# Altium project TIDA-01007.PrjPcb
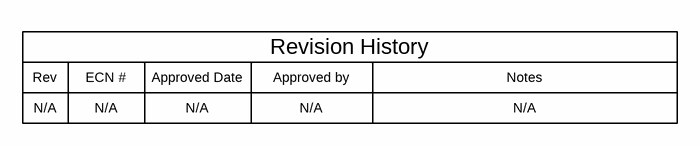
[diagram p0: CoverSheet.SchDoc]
CopyrightYear: 2015; EVM_Orderable: N/A; PCB_Layout: Summer Su; PCB_Rev: E1; PRJ_Customer: Public Release; PRJ_Engineer: Summer Su; PRJ_Number: TIDA-01007; PRJ_Title: Automotive EMC Compatible Rear Light with Sequential and Turn Function; SCH_Rev: E1; TechSupport: http://www.ti.com/support; TID: TIDA-01007
3 sheets, 83 parts. Net scope: global (net labels, ports and power ports of the same name join across sheets).
Board file: TIDA-01007.PcbDoc
Sheets:
  CoverSheet.SchDoc
  TIDA-01007_CoverSheet.SchDoc
  TID_Hardware.SchDoc

## Sheet CoverSheet.SchDoc
size 431 x 279 mm; Date: Not shown in title block; ApprovedBy: Not shown in title block; CheckedBy: Not shown in title block; Author: Not shown in title block; CompanyName: Not shown in title block; Engineer: Not shown in title block; Organization: Not shown in title block; Address1: Not shown in title block; Address2: Not shown in title block; Address3: Not shown in title block; Address4: Not shown in title block; DocumentNumber: 1; Revision: Use project parameter SCH_Rev; SheetNumber: 1; SheetTotal: 3; PageSetup: Record=PageOptions¦CenterHorizontal=True¦CenterVertical=True¦PrintScale=1.00¦XCorrection=1.00¦YCorrection=1.00¦PrintKind=0¦BorderSize=5000000¦LeftOffset=0¦BottomOffset=0¦Orientation=2¦PaperLength=1000¦PaperWidth=1000¦Scale=100¦PaperSource=15¦PrintQuality=600¦MediaType=1¦DitherType=10¦PaperKind=Letter¦PrintScaleMode=1

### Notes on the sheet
- Rev
- N/A
- ECN #
- Approved Date
- Approved by
- Revision History
- Notes

## Sheet TIDA-01007_CoverSheet.SchDoc
size 431 x 279 mm; Date: Not shown in title block; ApprovedBy: Not shown in title block; CheckedBy: Not shown in title block; Author: Not shown in title block; CompanyName: Not shown in title block; Engineer: Summer Su; Organization: Not shown in title block; Address1: Not shown in title block; Address2: Not shown in title block; Address3: Not shown in title block; Address4: Not shown in title block; DocumentNumber: 1; Revision: Use project parameter SCH_Rev; SheetNumber: 2; SheetTotal: 3; PageSetup: Record=PageOptions¦CenterHorizontal=True¦CenterVertical=True¦PrintScale=0.64¦XCorrection=1.00¦YCorrection=1.00¦PrintKind=0¦BorderSize=5000000¦LeftOffset=0¦BottomOffset=0¦Orientation=2¦PaperLength=1000¦PaperWidth=1000¦Scale=100¦PaperSource=15¦PrintQuality=600¦MediaType=1¦DitherType=10¦PrintScaleMode=1¦PaperKind=Letter
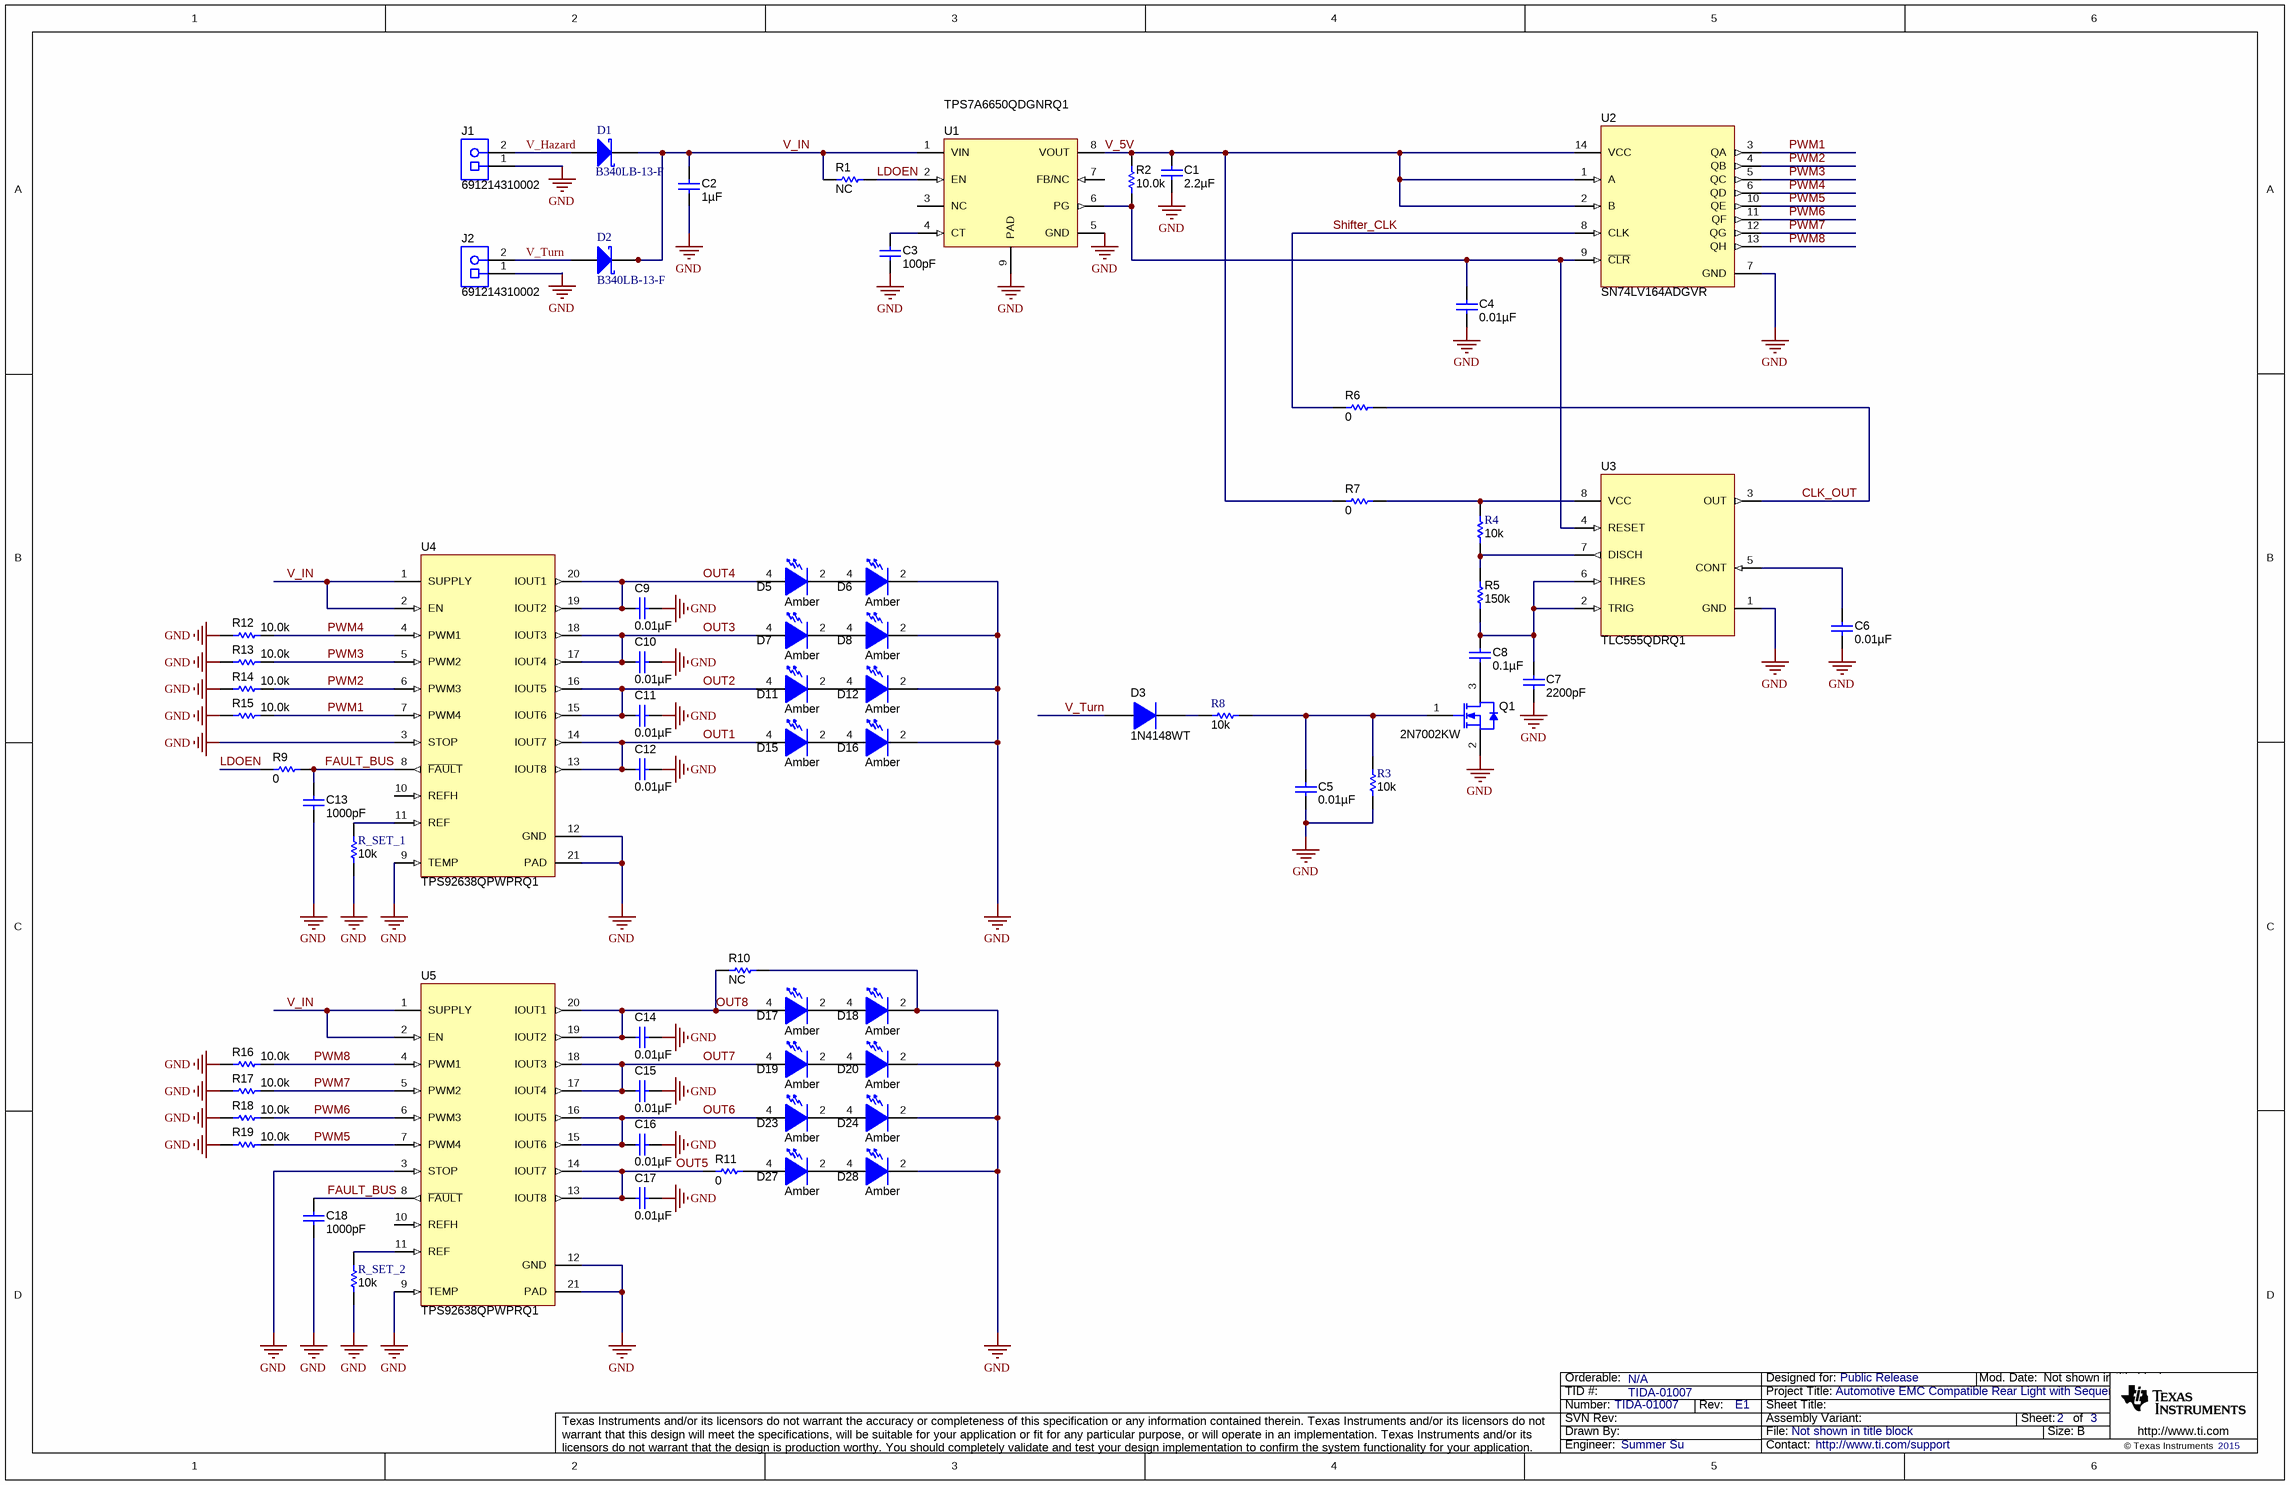
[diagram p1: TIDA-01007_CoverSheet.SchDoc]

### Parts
C1  ValueDisplayed: 2.2µF  [0805_HV]  (hidden comment: 0805YD225KAT2A)
C2  ValueDisplayed: 1µF  [0805_HV]  (hidden comment: 08055C105KAT2A)
C3  ValueDisplayed: 100pF  [0603]  (hidden comment: 06033C101KAT2A)
C4  ValueDisplayed: 0.01µF  [0603]  (hidden comment: CL10B103KB8NCNC)
C5  ValueDisplayed: 0.01µF  [0603]  (hidden comment: CL10B103KB8NCNC)
C6  ValueDisplayed: 0.01µF  [0603]  (hidden comment: CL10B103KB8NCNC)
C7  ValueDisplayed: 2200pF  [0603]  (hidden comment: C0603C222K5RAC)
C8  ValueDisplayed: 0.1µF  [0603]  (hidden comment: 0603YC104JAT2A)
C9  ValueDisplayed: 0.01µF  [0603]  (hidden comment: C0603C103K5RACTU)
C10  ValueDisplayed: 0.01µF  [0603]  (hidden comment: C0603C103K5RACTU)
C11  ValueDisplayed: 0.01µF  [0603]  (hidden comment: C0603C103K5RACTU)
C12  ValueDisplayed: 0.01µF  [0603]  (hidden comment: C0603C103K5RACTU)
C13  ValueDisplayed: 1000pF  [0603]  (hidden comment: C0603X102K5RACTU)
C14  ValueDisplayed: 0.01µF  [0603]  (hidden comment: C0603C103K5RACTU)
C15  ValueDisplayed: 0.01µF  [0603]  (hidden comment: C0603C103K5RACTU)
C16  ValueDisplayed: 0.01µF  [0603]  (hidden comment: C0603C103K5RACTU)
C17  ValueDisplayed: 0.01µF  [0603]  (hidden comment: C0603C103K5RACTU)
C18  ValueDisplayed: 1000pF  [0603]  (hidden comment: C0603X102K5RACTU)
D1  B340LB-13-F  [SMB]
D2  B340LB-13-F  [SMB]
D3  1N4148WT  [Fairchild_SOD-523F]
D5  value Amber  [LED_PowerTOPLED_GF_lens]  (hidden comment: LA E63F-EBGA-24-1-Z)
D6  value Amber  [LED_PowerTOPLED_GF_lens]  (hidden comment: LA E63F-EBGA-24-1-Z)
D7  value Amber  [LED_PowerTOPLED_GF_lens]  (hidden comment: LA E63F-EBGA-24-1-Z)
D8  value Amber  [LED_PowerTOPLED_GF_lens]  (hidden comment: LA E63F-EBGA-24-1-Z)
D11  value Amber  [LED_PowerTOPLED_GF_lens]  (hidden comment: LA E63F-EBGA-24-1-Z)
D12  value Amber  [LED_PowerTOPLED_GF_lens]  (hidden comment: LA E63F-EBGA-24-1-Z)
D15  value Amber  [LED_PowerTOPLED_GF_lens]  (hidden comment: LA E63F-EBGA-24-1-Z)
D16  value Amber  [LED_PowerTOPLED_GF_lens]  (hidden comment: LA E63F-EBGA-24-1-Z)
D17  value Amber  [LED_PowerTOPLED_GF_lens]  (hidden comment: LA E63F-EBGA-24-1-Z)
D18  value Amber  [LED_PowerTOPLED_GF_lens]  (hidden comment: LA E63F-EBGA-24-1-Z)
D19  value Amber  [LED_PowerTOPLED_GF_lens]  (hidden comment: LA E63F-EBGA-24-1-Z)
D20  value Amber  [LED_PowerTOPLED_GF_lens]  (hidden comment: LA E63F-EBGA-24-1-Z)
D23  value Amber  [LED_PowerTOPLED_GF_lens]  (hidden comment: LA E63F-EBGA-24-1-Z)
D24  value Amber  [LED_PowerTOPLED_GF_lens]  (hidden comment: LA E63F-EBGA-24-1-Z)
D27  value Amber  [LED_PowerTOPLED_GF_lens]  (hidden comment: LA E63F-EBGA-24-1-Z)
D28  value Amber  [LED_PowerTOPLED_GF_lens]  (hidden comment: LA E63F-EBGA-24-1-Z)
J1  691214310002  [Wurth_691214310002]
J2  691214310002  [Wurth_691214310002]
Q1  2N7002KW  [SOT-323]
R1  ValueDisplayed: NC  [0603]  (hidden comment: RG1608P-103-B-T5)
R2  ValueDisplayed: 10.0k  [0603]  (hidden comment: RG1608P-103-B-T5)
R3  value 10k  [0603]  (hidden comment: CRCW060310K0FKEA)
R4  value 10k  [0603]  (hidden comment: CRCW060310K0FKEA)
R5  ValueDisplayed: 150k  [0603]  (hidden comment: CRCW0603150KFKEA)
R6  ValueDisplayed: 0  [0603]  (hidden comment: CRCW06030000Z0EA)
R7  ValueDisplayed: 0  [0603]  (hidden comment: CRCW06030000Z0EA)
R8  value 10k  [0603]  (hidden comment: CRCW060310K0FKEA)
R9  ValueDisplayed: 0  [0603]  (hidden comment: CRCW06030000Z0EA)
R10  ValueDisplayed: NC  [0805_HV]  (hidden comment: CRCW08050000Z0EA)
R11  ValueDisplayed: 0  [0805_HV]  (hidden comment: CRCW08050000Z0EA)
R12  ValueDisplayed: 10.0k  [0603]  (hidden comment: RG1608P-103-B-T5)
R13  ValueDisplayed: 10.0k  [0603]  (hidden comment: RG1608P-103-B-T5)
R14  ValueDisplayed: 10.0k  [0603]  (hidden comment: RG1608P-103-B-T5)
R15  ValueDisplayed: 10.0k  [0603]  (hidden comment: RG1608P-103-B-T5)
R16  ValueDisplayed: 10.0k  [0603]  (hidden comment: RG1608P-103-B-T5)
R17  ValueDisplayed: 10.0k  [0603]  (hidden comment: RG1608P-103-B-T5)
R18  ValueDisplayed: 10.0k  [0603]  (hidden comment: RG1608P-103-B-T5)
R19  ValueDisplayed: 10.0k  [0603]  (hidden comment: RG1608P-103-B-T5)
R_SET_1  value 10k  [0603]  (hidden comment: CRCW060310K0FKEA)
R_SET_2  value 10k  [0603]  (hidden comment: CRCW060310K0FKEA)
U1  TPS7A6650QDGNRQ1  [DGN0008D_N]
U2  SN74LV164ADGVR  [DGV0014A_N]
U3  TLC555QDRQ1  [D0008A_N]
U4  TPS92638QPWPRQ1  [PWP0020D_N]
U5  TPS92638QPWPRQ1  [PWP0020D_N]

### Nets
GND: C1.2 C2.2 C3.2 C4.2 C5.2 C6.2 C7.2 C9.2 C10.2 C11.2 C12.2 C13.2 C14.2 C15.2 C16.2 C17.2 C18.2 D6.2(K) D8.2(K) D12.2(K) D16.2(K) D18.2(K) D20.2(K) D24.2(K) D28.2(K) J1.1 J2.1 Q1.2(S) R3.2 R10.2 R12.2 R13.2 R14.2 R15.2 R16.2 R17.2 R18.2 R19.2 R_SET_1.2 R_SET_2.2 U1.5(GND) U1.9(PAD) U2.7(GND) U3.1(GND) U4.3(STOP) U4.9(TEMP) U4.12(GND) U4.21(PAD) U5.3(STOP) U5.9(TEMP) U5.12(GND) U5.21(PAD)
CLK_OUT: R6.2 U3.3(OUT)
FAULT_BUS: C13.1 C18.1 R9.2 U4.8(~{FAULT}) U5.8(~{FAULT})
LDOEN: R1.2 R9.1 U1.2(EN)
OUT1: C12.1 D15.4(A) U4.13(IOUT8) U4.14(IOUT7)
OUT2: C11.1 D11.4(A) U4.15(IOUT6) U4.16(IOUT5)
OUT3: C10.1 D7.4(A) U4.17(IOUT4) U4.18(IOUT3)
OUT4: C9.1 D5.4(A) U4.19(IOUT2) U4.20(IOUT1)
OUT5: C17.1 R11.1 U5.13(IOUT8) U5.14(IOUT7)
OUT6: C16.1 D23.4(A) U5.15(IOUT6) U5.16(IOUT5)
OUT7: C15.1 D19.4(A) U5.17(IOUT4) U5.18(IOUT3)
OUT8: C14.1 D17.4(A) R10.1 U5.19(IOUT2) U5.20(IOUT1)
PWM1: R15.1 U2.3(QA) U4.7(PWM4)
PWM2: R14.1 U2.4(QB) U4.6(PWM3)
PWM3: R13.1 U2.5(QC) U4.5(PWM2)
PWM4: R12.1 U2.6(QD) U4.4(PWM1)
PWM5: R19.1 U2.10(QE) U5.7(PWM4)
PWM6: R18.1 U2.11(QF) U5.6(PWM3)
PWM7: R17.1 U2.12(QG) U5.5(PWM2)
PWM8: R16.1 U2.13(QH) U5.4(PWM1)
Shifter_CLK: R6.1 U2.8(CLK)
V_5V: C1.1 R2.2 R7.1 U1.8(VOUT) U2.1(A) U2.2(B) U2.14(VCC)
V_Hazard: D1.2(A) J1.2
V_IN: C2.1 D1.1(K) D2.1(K) R1.1 U1.1(VIN) U4.1(SUPPLY) U4.2(EN) U5.1(SUPPLY) U5.2(EN)
V_Turn: D2.2(A) D3.2(A) J2.2
NetC3_1: C3.1 U1.4(CT)
NetC4_1: C4.1 R2.1 U1.6(PG) U2.9(~{CLR}) U3.4(RESET)
NetC5_1: C5.1 Q1.1(G) R3.1 R8.2
NetC6_1: C6.1 U3.5(CONT)
NetC7_1: C7.1 C8.1 R5.1 U3.2(TRIG) U3.6(THRES)
NetC8_2: C8.2 Q1.3(D)
NetD3_1: D3.1(K) R8.1
NetD5_2: D5.2(K) D6.4(A)
NetD7_2: D7.2(K) D8.4(A)
NetD11_2: D11.2(K) D12.4(A)
NetD15_2: D15.2(K) D16.4(A)
NetD17_2: D17.2(K) D18.4(A)
NetD19_2: D19.2(K) D20.4(A)
NetD23_2: D23.2(K) D24.4(A)
NetD27_2: D27.2(K) D28.4(A)
NetD27_4: D27.4(A) R11.2
NetR4_1: R4.1 R7.2 U3.8(VCC)
NetR4_2: R4.2 R5.2 U3.7(DISCH)
NetR_SET_1_1: R_SET_1.1 U4.11(REF)
NetR_SET_2_1: R_SET_2.1 U5.11(REF)

Not connected (* = marked no-connect by the designer): U1 3(NC) 7(FB/NC); U4 10(REFH); U5 10(REFH)

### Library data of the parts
C1 = 0805YD225KAT2A: CAP, CERM, 2.2 µF, 16 V, +/- 10%, X5R, 0805; Manufacturer: AVX; Polarized: N; CompType: Capacitor; Value: 2.2uF; U/M: EA; Cap_F: 0.0000022; Tolerance_%: 10; ESR_ohm: 0.009; Value1: 0.009 ohm; VDC_V: 16; Value2: 16V; TaMin_C: -55; TaMax_C: 85; Cap_Case: 0805
C2 = 08055C105KAT2A: CAP, CERM, 1 µF, 50 V, +/- 10%, X7R, 0805; Manufacturer: AVX; Polarized: N; CompType: Capacitor; Value: 1uF; U/M: EA; Cap_F: 0.000001; Tolerance_%: 10; Value1: Unknown; VDC_V: 50; Value2: 50V; TaMin_C: -55; TaMax_C: 125; Cap_Case: 0805
C3 = 06033C101KAT2A: CAP, CERM, 100 pF, 25 V, +/- 10%, X7R, 0603; Manufacturer: AVX; Polarized: N; CompType: Capacitor; Value: 100pF; U/M: EA; Cap_F: 0.0000000001; Tolerance_%: 10; Value1: Unknown; VDC_V: 25; Value2: 25V; TaMin_C: -55; TaMax_C: 125
C4-C6 = CL10B103KB8NCNC: CAP, CERM, 0.01 µF, 50 V, +/- 10%, X7R, 0603; Manufacturer: Samsung Electro-Mechanics; Polarized: N; CompType: Capacitor; Value: 0.01uF; U/M: EA; Cap_F: 0.00000001; Tolerance_%: 10; Value1: Unknown; VDC_V: 50; Value2: 50V; TaMin_C: -55; TaMax_C: 125
C7 = C0603C222K5RAC: CAP, CERM, 2200 pF, 50 V, +/- 10%, X7R, 0603; Manufacturer: Kemet; Polarized: N; CompType: Capacitor; Value: 2200pF; U/M: EA; Cap_F: 0.0000000022; Tolerance_%: 10; Value1: Unknown; VDC_V: 50; Value2: 50V; TaMin_C: -55; TaMax_C: 125
C8 = 0603YC104JAT2A: CAP, CERM, 0.1 µF, 16 V, +/- 5%, X7R, 0603; Manufacturer: AVX; Polarized: N; CompType: Capacitor; Value: 0.1uF; U/M: EA; Cap_F: 0.0000001; Tolerance_%: 5; ESR_ohm: 0.039; Value1: 0.039 ohm; VDC_V: 16; Value2: 16V; TaMin_C: -55; TaMax_C: 125
C9-C12 C14-C17 = C0603C103K5RACTU: CAP, CERM, 0.01 µF, 50 V, +/- 10%, X7R, 0603; Manufacturer: Kemet; Polarized: N; CompType: Capacitor; Value: 0.01uF; U/M: EA; Cap_F: 0.00000001; Tolerance_%: 10; Value1: Unknown; VDC_V: 50; Value2: 50V; TaMin_C: -55; TaMax_C: 125
C13 C18 = C0603X102K5RACTU: CAP, CERM, 1000 pF, 50 V, +/- 10%, X7R, 0603; Manufacturer: Kemet; Polarized: N; CompType: Capacitor; Value: 1000pF; U/M: EA; Cap_F: 0.000000001; Tolerance_%: 10; Value1: Unknown; VDC_V: 50; Value2: 50V; TaMin_C: -55; TaMax_C: 125
D1 D2 = B340LB-13-F: Diode, Schottky, 40V, 3A, SMB; Manufacturer: Diodes Inc.; Value: 0.45V; U/M: EA; Vf_V: 0.45; Io_A: 3; Vr_V: 40; TJmax_C: 125; RJC_CperW: 25
D3 = 1N4148WT: Diode, Switching, 75 V, 0.3 A, SMD, 2-Leads, Body 1.2x0.8mm; Manufacturer: Fairchild Semiconductor; U/M: EA; Value: 75V; Value1: 0.3A; Io_A: 0.3; Vr_V: 75; TJmax_C: 150
D5-D8 D11 D12 D15-D20 D23 D24 D27 D28 = LA E63F-EBGA-24-1-Z: LED, Amber, SMD; Manufacturer: OSRAM; Type: AlInGaP; Vf_V: 2.15; Value2: 2.15V; Io_A: 0.05; Vr_V: 12; RJC_CperW: 130; Tjmax_C: 125; Power_TotalModule: 0.1075; Value1: 0.1075W; LambdaP: 624; LambdaD: 617; NumParallelLEDs: 1; LuminousFlux_PhiV: 4.3; Angle: 30; FamilyName: Power TOPLED&#174;; U/M: EA
J1 J2 = 691214310002: Terminal Block, 2x1, 3.81mm, 24-16 AWG, 10A, 300VAC, TH; Manufacturer: Wurth Elektronik; SymbolCreator: a0412235; U/M: EA
Q1 = 2N7002KW: MOSFET, N-CH, 60 V, 0.31 A, SOT-323; Manufacturer: Fairchild Semiconductor; Alternate Manufacturer: None; U/M: EA; ChType: N; Value: 60V; VdsMax_V: 60; Value1: 1.6 ohm; Rdson45_ohm: 1.6; Value2: ? nC; Vgs_V: 2.1; IdsMax_A: 0.31
R1 R2 R12-R19 = RG1608P-103-B-T5: RES, 10.0 k, 0.1%, 0.1 W, 0603; Manufacturer: Susumu Co Ltd; CompType: Resistor; Value: 10.0k; Res_ohm: 10000; Value_Code: 10k0; Tolerance_%: 0.1; Value2: 0.1W; VDC_V: 75; TempCo: 25 ppm/C; EIA_Code: E192; U/M: EA
R3 R4 R8 R_SET_1 R_SET_2 = CRCW060310K0FKEA: RES, 10.0k ohm, 1%, 0.1W, 0603; Manufacturer: Vishay-Dale; CompType: Resistor; Res_ohm: 10000; Value_Code: 10k0; Tolerance_%: 1; Power_W: 0.1; VDC_V: 75; TempCo: 100 ppm/C; EIA_Code: E96; U/M: EA
R5 = CRCW0603150KFKEA: RES, 150 k, 1%, 0.1 W, 0603; Manufacturer: Vishay-Dale; CompType: Resistor; Value: 150k; Res_ohm: 150000; Tolerance_%: 1; Power_W: 0.1; Value2: 0.1W; VDC_V: 75; TempCo: 100 ppm/C; EIA_Code: E96; U/M: EA
R6 R7 R9 = CRCW06030000Z0EA: RES, 0, 5%, 0.1 W, 0603; Manufacturer: Vishay-Dale; CompType: Resistor; Value: 0; Value_Code: 0000; Tolerance_%: 5; Power_W: 0.1; Value2: 0.1W; VDC_V: 75; TempCo: 200 ppm/C; EIA_Code: E24; U/M: EA
R10 R11 = CRCW08050000Z0EA: RES, 0, 5%, 0.125 W, 0805; Manufacturer: Vishay-Dale; CompType: Resistor; Value: 0; Value_Code: 0000; Tolerance_%: 5; Power_W: 0.125; Value2: 0.125W; VDC_V: 150; TempCo: 200 ppm/C; EIA_Code: E24; U/M: EA
U1 = TPS7A6650QDGNRQ1: High-Voltage Ultralow-Iq Low-Dropout Regulator, DGN0008D; Manufacturer: Texas Instruments; SymbolCreator: a0411947; CompType: IC; U/M: EA
U2 = SN74LV164ADGVR: 8-BIT PARALLEL-OUT SERIAL SHIFT REGISTERS, DGV0014A; Manufacturer: Texas Instruments; SymbolCreator: Altium; CompType: IC; U/M: EA
U3 = TLC555QDRQ1: LinCMOS Timer, D0008A; Manufacturer: Texas Instruments; SymbolCreator: a0799628; CompType: IC; U/M: EA
U4 U5 = TPS92638QPWPRQ1: Eight-Channel Linear LED Driver with PWM Dimming, PWP0020D; Manufacturer: Texas Instruments; SymbolCreator: a0411947; CompType: IC; U/M: EA

## Sheet TID_Hardware.SchDoc
size 431 x 279 mm; Date: Not shown in title block; ApprovedBy: Not shown in title block; CheckedBy: Not shown in title block; Author: Not shown in title block; CompanyName: Not shown in title block; Engineer: Not shown in title block; Organization: Not shown in title block; Address1: Not shown in title block; Address2: Not shown in title block; Address3: Not shown in title block; Address4: Not shown in title block; DocumentNumber: 1; Revision: Use project parameter SCH_Rev; SheetNumber: 3; SheetTotal: 3; PageSetup: Record=PageOptions¦CenterHorizontal=True¦CenterVertical=True¦PrintScale=1.00¦XCorrection=1.00¦YCorrection=1.00¦PrintKind=0¦BorderSize=5000000¦LeftOffset=0¦BottomOffset=0¦Orientation=2¦PaperLength=1000¦PaperWidth=1000¦Scale=100¦PaperSource=15¦PrintQuality=600¦MediaType=1¦DitherType=10¦PaperKind=Letter¦PrintScaleMode=1
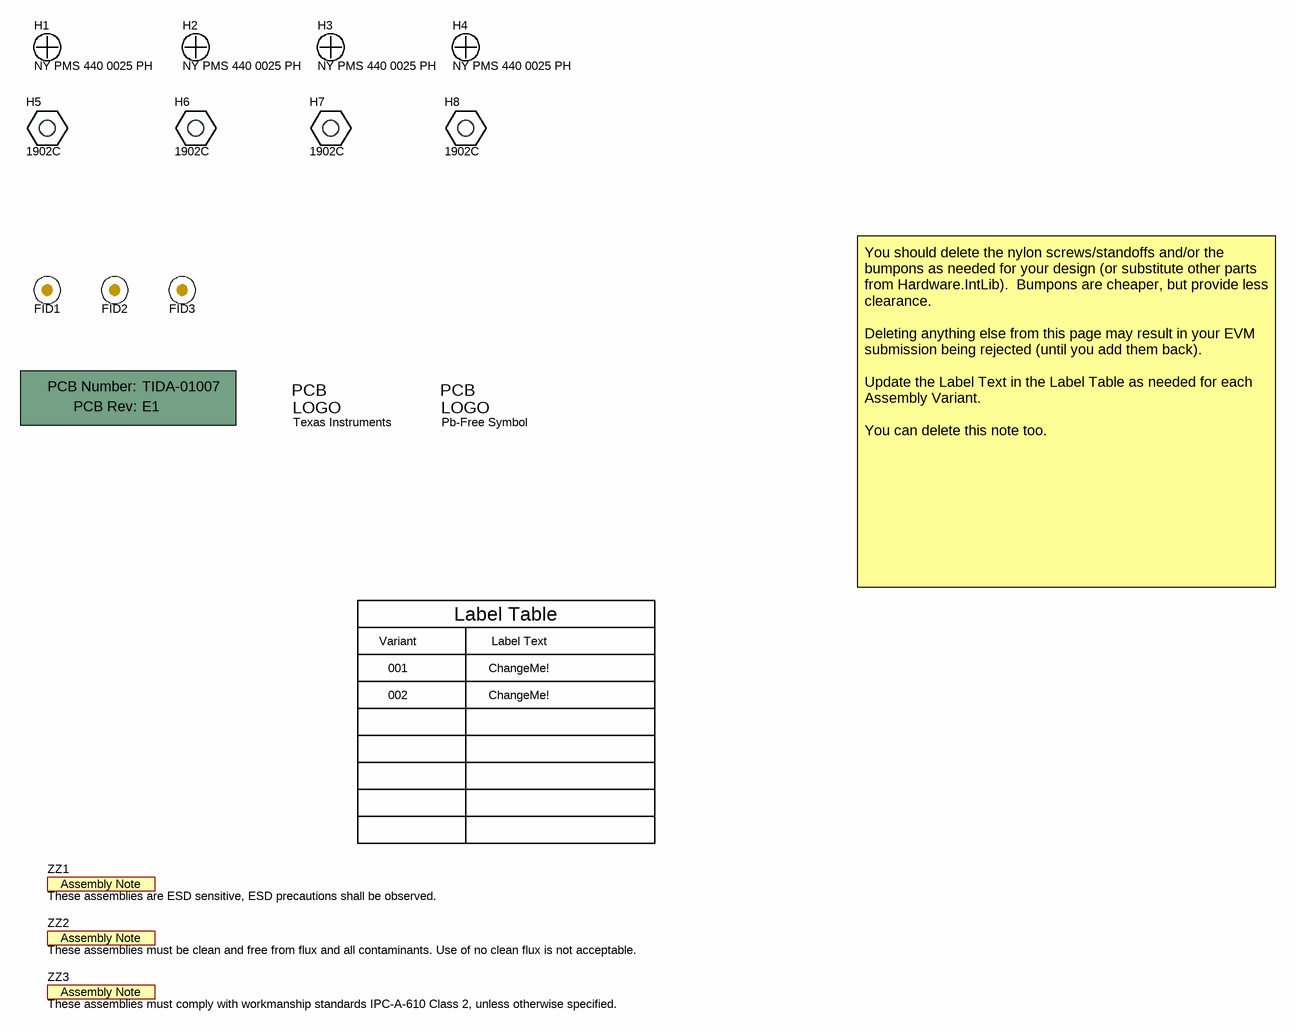
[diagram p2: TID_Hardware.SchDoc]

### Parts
!PCB1  Printed Circuit Board  (value not drawn)  (mechanical)
FID1  Fiducial  [Fiducial10-20]  (value not drawn)
FID2  Fiducial  [Fiducial10-20]  (value not drawn)
FID3  Fiducial  [Fiducial10-20]  (value not drawn)
H1  NY PMS 440 0025 PH  [NY PMS 440 0025 PH]
H2  NY PMS 440 0025 PH  [NY PMS 440 0025 PH]
H3  NY PMS 440 0025 PH  [NY PMS 440 0025 PH]
H4  NY PMS 440 0025 PH  [NY PMS 440 0025 PH]
H5  1902C  [Keystone_1902C]
H6  1902C  [Keystone_1902C]
H7  1902C  [Keystone_1902C]
H8  1902C  [Keystone_1902C]
Logo1  Texas Instruments  [TI_Stacked_Overlay_Small]  (no BOM)
Logo2  Pb-Free Symbol  [Pb-Free_Overlay_Small]  (no BOM)
ZZ1  These assemblies are ESD sensitive, ESD precautions shall be observed.  [AssemblyNote]  (no BOM)
ZZ2  These assemblies must be clean and free from flux and all contaminants. Use of no clean flux is not acceptable.  [AssemblyNote]  (no BOM)
ZZ3  These assemblies must comply with workmanship standards IPC-A-610 Class 2, unless otherwise specified.  [AssemblyNote]  (no BOM)

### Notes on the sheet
- Variant
- Label Table
- Label Text
- You should delete the nylon screws/standoffs and/or the bumpons as needed for your design (or substitute other parts from Hardware.IntLib).  Bumpons are cheaper, but provide less clearance.
  Deleting anything else from this page may result in your EVM submission being rejected (until you add them back).
  Update the Label Text in the Label Table as needed for each Assembly Variant.
  You can delete this note too.
- 001
- 002
- ChangeMe!

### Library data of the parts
!PCB1 = PCB: Manufacturer: Any; PartNumber: TIDA-01007; SymbolCreator: a0412235
FID1-FID3 = Fiducial: Fiducial mark.  There is nothing to buy or mount.; SymbolCreator: codlsc
H1-H4 = NY PMS 440 0025 PH: Machine Screw, Round, #4-40 x 1/4, Nylon, Philips panhead; Manufacturer: B&F Fastener Supply; CompType: Hardware; SymbolCreator: codlsc; U/M: EA
H5-H8 = 1902C: Standoff, Hex, 0.5"L #4-40 Nylon; Manufacturer: Keystone; CompType: Hardware
Logo1 = TI_Logo: Texas Instrument Corporate Signature; SymbolCreator: codlsc
Logo2 = Pb-Free: SymbolCreator: a0412235
ZZ1-ZZ3 = AssemblyNote: SymbolCreator: codlsc

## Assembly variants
001: not fitted FID1 FID2 FID3 R1 R10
